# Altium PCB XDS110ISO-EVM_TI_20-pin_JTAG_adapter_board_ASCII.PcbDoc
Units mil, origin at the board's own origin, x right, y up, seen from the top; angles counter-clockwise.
Board outline 1100 x 500.17 mil, 2 copper layers (Top Signal, Bottom Signal), stack 58.8 mil thick; 2 components, 6 nets, 35 pads, 16 vias.
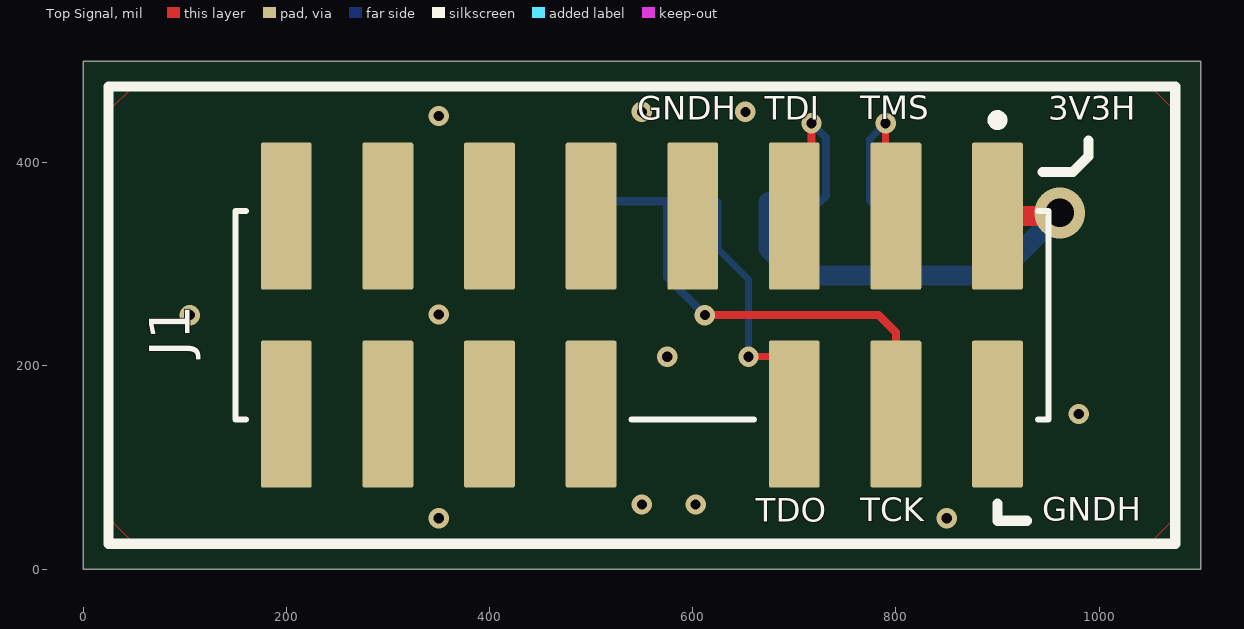
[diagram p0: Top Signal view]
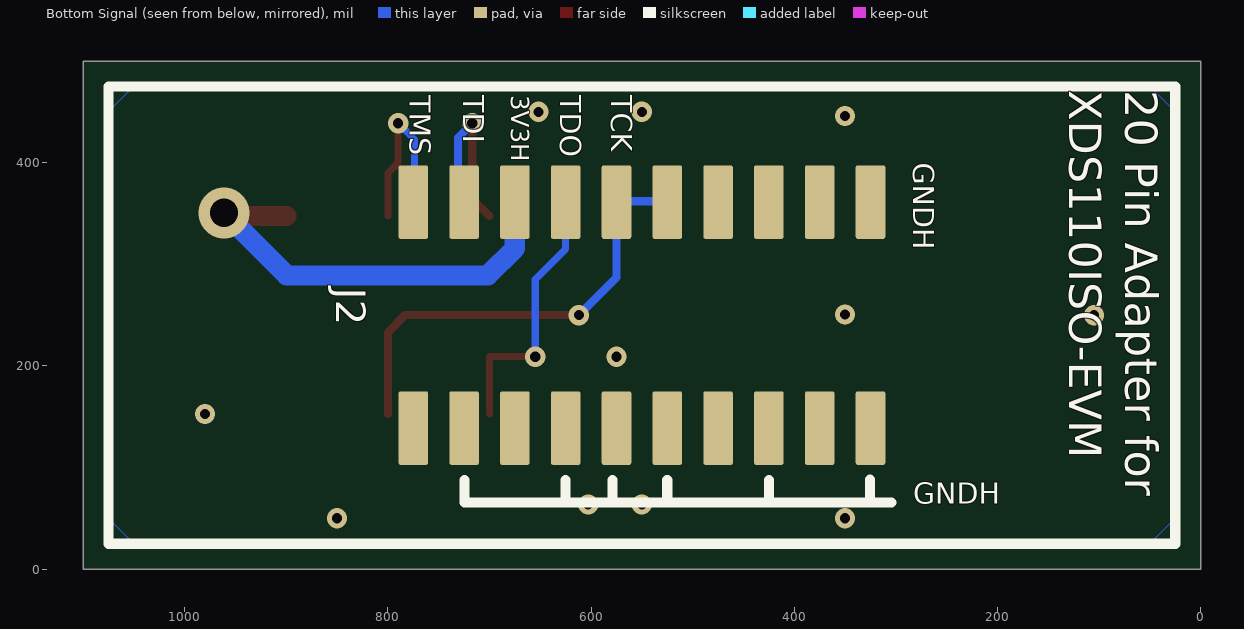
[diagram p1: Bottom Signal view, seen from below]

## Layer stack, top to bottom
Top Solder: solder mask 0.4, Solder Resist, Dk 3.5
Top Signal: signal copper 1.4
Dielectric 1: prepreg 8, FR-4, Dk 4.2
Dielectric 2: core 40, FR-4, Dk 4.2
Dielectric 3: prepreg 8, FR-4, Dk 4.2
Bottom Signal: signal copper 1.4
Bottom Solder: solder mask 0.4, Solder Resist, Dk 3.5

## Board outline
0,-0.17 0,500 1100,500 1100,-0.17

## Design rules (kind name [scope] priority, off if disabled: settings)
AcuteAngle [All] p0: scope1count=1 scope1_0_kind=Board scope1_0_value=Board scope2count=1 scope2_0_kind=Board scope2_0_value=Board commentlength=0 minimum=4.50000000000000E+0001
AcuteAngle [All] p1: minimum=4.50000000000000E+0001 checktracksonly=TRUE
AssemblyTestPointUsage [All] p0: scope1count=1 scope1_0_kind=Board scope1_0_value=Board scope2count=1 scope2_0_kind=Board scope2_0_value=Board commentlength=0
AssemblyTestPointUsage [All] p1: valid=2
AssemblyTestpoint [All] p0: scope1count=1 scope1_0_kind=Board scope1_0_value=Board scope2count=1 scope2_0_kind=Board scope2_0_value=Board commentlength=0
BoardOutlineClearance BoardOutlineClearance_USB101 [All] p0: scope1count=1 scope1_0_kind=Component scope1_0_value=USB101 scope2count=1 scope2_0_kind=Board scope2_0_value=Board commentlength=0 gap=0
BoardOutlineClearance [All] p0 off: scope1count=1 scope1_0_kind=Board scope1_0_value=Board scope2count=1 scope2_0_kind=Board scope2_0_value=Board commentlength=172 gap=10 // Protel DXP Scope 1 Expression Was: OnCopper and Not InComponentClass('Logo') and not InComponentClass('FiducialMark') and not InRegion(1000,500,4000,800) and not InPoly
BoardOutlineClearance BoardOutlineClearance_Poly [All] p0 off: scope1count=1 scope1_0_kind=Board scope1_0_value=Board scope2count=1 scope2_0_kind=Board scope2_0_value=Board commentlength=58 gap=25 // Protel DXP Scope 1 Expression Was: OnCopper and IsPoly
BoardOutlineClearance BoardOutlineClearance_MountingHoles [All] p0 off: scope1count=1 scope1_0_kind=Board scope1_0_value=Board scope2count=1 scope2_0_kind=Board scope2_0_value=Board commentlength=86 gap=40 // Protel DXP Scope 1 Expression Was: OnCopper and InComponentClass('Mounting Holes')
BoardOutlineClearance BoardOutlineClearance_MountingHoles [OnCopper and InComponentClass('Mounting Holes')] p1: gap=40 ignorepadtopadclearanceinfootprint=FALSE
BoardOutlineClearance BoardOutlineClearance_Poly [OnCopper and IsPoly] p2: gap=25 ignorepadtopadclearanceinfootprint=FALSE
BoardOutlineClearance BoardOutlineClearance_USB101 [InComponent('USB101')] p3: gap=0 ignorepadtopadclearanceinfootprint=FALSE
BoardOutlineClearance [OnCopper and Not InComponentClass('Logo') and not InComponentClass('FiducialMark') and not InRegion(1000,500,4000,800) and not InPoly] p4: gap=10 ignorepadtopadclearanceinfootprint=FALSE
Clearance Clearance_PTH [All] p0 off: scope1count=1 scope1_0_kind=Board scope1_0_value=Board scope2count=1 scope2_0_kind=Board scope2_0_value=Board commentlength=56 gap=7 // Protel DXP Scope 1 Expression Was: HoleDiameter > 10
Clearance Clearance_NPTH [All] p0 off: scope1count=1 scope1_0_kind=Board scope1_0_value=Board scope2count=1 scope2_0_kind=Board scope2_0_value=Board commentlength=56 gap=15 // Protel DXP Scope 1 Expression Was: HoleDiameter = 39
Clearance Clearance_FiducialMark [All] p0: scope1count=1 scope1_0_kind=ComponentClass scope1_0_value=FiducialMark scope2count=1 scope2_0_kind=ComponentClass scope2_0_value=FiducialMark commentlength=0 gap=0
Clearance Clearance_Boardedge [All] p0 off: scope1count=1 scope1_0_kind=Board scope1_0_value=Board scope2count=1 scope2_0_kind=Board scope2_0_value=Board commentlength=48 gap=11.8 // Protel DXP Scope 2 Expression Was: IsKeepOut
Clearance [All] p0: scope1count=1 scope1_0_kind=Board scope1_0_value=Board scope2count=1 scope2_0_kind=Board scope2_0_value=Board commentlength=0 gap=6
Clearance Clearance_NPTH [HoleDiameter = 39] p1: gap=15 ignorepadtopadclearanceinfootprint=FALSE
Clearance Clearance_PTH [HoleDiameter > 10] p2: gap=7 ignorepadtopadclearanceinfootprint=FALSE
Clearance Clearance_FiducialMark [InComponentClass('FiducialMark') vs InComponentClass('FiducialMark')] p3: gap=0 ignorepadtopadclearanceinfootprint=FALSE
Clearance Clearance_Boardedge [All vs IsKeepOut] p4: gap=11.8 ignorepadtopadclearanceinfootprint=FALSE
Clearance [All] p5: gap=6 ignorepadtopadclearanceinfootprint=FALSE
ComponentClearance ComponentClearance_THtoTH [All] p0 off: scope1count=1 scope1_0_kind=Board scope1_0_value=Board scope2count=1 scope2_0_kind=Board scope2_0_value=Board commentlength=54 gap=20 collisioncheckmode=3 // Protel DXP Scope 2 Expression Was: IsThruComponent
ComponentClearance ComponentClearance_THtoSMT [All] p0 off: scope1count=1 scope1_0_kind=Board scope1_0_value=Board scope2count=1 scope2_0_kind=Board scope2_0_value=Board commentlength=53 gap=10 collisioncheckmode=3 // Protel DXP Scope 2 Expression Was: IsSMTComponent
ComponentClearance ComponentClearance_SmallPassives [All] p0 off: scope1count=1 scope1_0_kind=Board scope1_0_value=Board scope2count=1 scope2_0_kind=Board scope2_0_value=Board commentlength=508 gap=10 collisioncheckmode=3 // Protel DXP Scope 2 Expression Was: HasFootprint('0201*') or HasFootprint('0402*') or HasFootprint('0508') or HasFootprint('0603*') or HasFootprint('0612') or HasFootprint('0805*') or HasFootprint('0815*') or HasFootprint('0830*') or HasFootprint('1206*') or HasFootprint('1210*') or HasFootprint('1808*') or HasFootprint('1812*') or HasFootprint('1825*') or HasFootprint('2010*') or HasFootprint('2220*') or HasFootprint('2225*') or HasFootprint('2512*') or HasFootprint('2728*') or HasFootprint('3518*')
ComponentClearance ComponentClearance_MountingHoles [All] p0 off: scope1count=1 scope1_0_kind=ComponentClass scope1_0_value="Mounting Holes" scope2count=1 scope2_0_kind=Board scope2_0_value=Board commentlength=0 gap=250 collisioncheckmode=3
ComponentClearance ComponentClearance_ScrewToNut [All] p0 off: scope1count=1 scope1_0_kind=Board scope1_0_value=Board scope2count=1 scope2_0_kind=Board scope2_0_value=Board commentlength=71 gap=3.94 collisioncheckmode=3 // Protel DXP Scope 2 Expression Was: (HasFootprint('Keystone_1902C'))
ComponentClearance ComponentClearance_Logo [All] p0: scope1count=1 scope1_0_kind=ComponentClass scope1_0_value=Logo scope2count=1 scope2_0_kind=Board scope2_0_value=Board commentlength=0 gap=0 collisioncheckmode=3
ComponentClearance ComponentClearance_Shunt [All] p0: scope1count=1 scope1_0_kind=ComponentClass scope1_0_value=Header scope2count=1 scope2_0_kind=ComponentClass scope2_0_value=Shunt commentlength=0 gap=0 collisioncheckmode=3
ComponentClearance ComponentClearance_MountingHoles_FiducialMarks [All] p0: scope1count=1 scope1_0_kind=ComponentClass scope1_0_value="Mounting Holes" scope2count=1 scope2_0_kind=ComponentClass scope2_0_value=FiducialMark commentlength=0 gap=50 collisioncheckmode=3
ComponentClearance ComponentClearance_Logo_1 [All] p0: scope1count=1 scope1_0_kind=ComponentClass scope1_0_value=Logo scope2count=1 scope2_0_kind=ComponentClass scope2_0_value=Logo commentlength=0 gap=0 collisioncheckmode=3
ComponentClearance "ComponentClearance_overlay to overlay" [All] p0 off: scope1count=1 scope1_0_kind=Board scope1_0_value=Board scope2count=1 scope2_0_kind=Board scope2_0_value=Board commentlength=54 gap=0 collisioncheckmode=3 // Protel DXP Scope 2 Expression Was: OnTopSilkscreen
ComponentClearance "ComponentClearance_overlay to overlay" [OnBottomSilkscreen vs OnTopSilkscreen] p1: gap=0 collisioncheckmode=3 verticalgap=0 showdistances=FALSE
ComponentClearance ComponentClearance_MountingHoles_FiducialMarks [InComponentClass('Mounting Holes') vs InComponentClass('FiducialMark')] p2: gap=50 collisioncheckmode=3 verticalgap=10 showdistances=FALSE
ComponentClearance ComponentClearance_Shunt [InComponentClass('Header') vs InComponentClass('Shunt')] p3: gap=0 collisioncheckmode=3 verticalgap=0 showdistances=FALSE
ComponentClearance ComponentClearance_Logo [InComponentClass('Logo')] p4: gap=0 collisioncheckmode=3 verticalgap=0 showdistances=FALSE
ComponentClearance ComponentClearance_Logo_1 [InComponentClass('Logo') vs InComponentClass('Logo')] p5: gap=0 collisioncheckmode=3 verticalgap=0 showdistances=FALSE
ComponentClearance ComponentClearance_ScrewToNut [(HasFootprint('NY PMS 440 0025 PH')) vs (HasFootprint('Keystone_1902C'))] p6: gap=3.94 collisioncheckmode=3 verticalgap=3.94 showdistances=FALSE
ComponentClearance ComponentClearance_MountingHoles [InComponentClass('Mounting Holes')] p7 off: gap=250 collisioncheckmode=3 verticalgap=100000 showdistances=FALSE
ComponentClearance ComponentClearance_SmallPassives [HasFootprint('0201*') or HasFootprint('0402*') or HasFootprint('0508') or HasFootprint('0603*') or HasFootprint('0612') or HasFootprint('0805*') or HasFootprint('0815*') or HasFootprint('0830*') or HasFootprint('1206*') or HasFootprint('1210*') or HasFootprint('1808*') or HasFootprint('1812*') or HasFootprint('1825*') or HasFootprint('2010*') or HasFootprint('2220*') or HasFootprint('2225*') or HasFootprint('2512*') or HasFootprint('2728*') or HasFootprint('3518*') vs HasFootprint('0201*') or HasFootprint('0402*') or HasFootprint('0508') or HasFootprint('0603*') or HasFootprint('0612') or HasFootprint('0805*') or HasFootprint('0815*') or HasFootprint('0830*') or HasFootprint('1206*') or HasFootprint('1210*') or HasFootprint('1808*') or HasFootprint('1812*') or HasFootprint('1825*') or HasFootprint('2010*') or HasFootprint('2220*') or HasFootprint('2225*') or HasFootprint('2512*') or HasFootprint('2728*') or HasFootprint('3518*')] p8 off: gap=10 collisioncheckmode=3 verticalgap=0 showdistances=FALSE
ComponentClearance ComponentClearance_THtoSMT [IsThruComponent vs IsSMTComponent] p9 off: gap=10 collisioncheckmode=3 verticalgap=10 showdistances=FALSE
ComponentClearance ComponentClearance_THtoTH [IsThruComponent vs IsThruComponent] p10 off: gap=20 collisioncheckmode=3 verticalgap=30 showdistances=FALSE
DiffPairsRouting [All] p0: scope1count=1 scope1_0_kind=Board scope1_0_value=Board scope2count=1 scope2_0_kind=Board scope2_0_value=Board commentlength=0
DiffPairsRouting [All] p1: maxlimit=100 minlimit=6 mostfreqgap=6 toplayer_minwidth=5.91 toplayer_maxwidth=15 toplayer_prefwidth=10.63 bottomlayer_minwidth=5.91 bottomlayer_maxwidth=15 bottomlayer_prefwidth=10.63 maxuncoupledlength=1000
FabricationTestPointUsage TestPointUsage [All] p0: scope1count=1 scope1_0_kind=Board scope1_0_value=Board scope2count=1 scope2_0_kind=Board scope2_0_value=Board commentlength=0 valid=2 allowmultiple=FALSE
FabricationTestPointUsage TestPointUsage [All] p1: valid=2 allowmultiple=FALSE
FabricationTestpoint Testpoint [All] p0: scope1count=1 scope1_0_kind=Board scope1_0_value=Board scope2count=1 scope2_0_kind=Board scope2_0_value=Board commentlength=0 side=3 testpointundercomponent=TRUE minsize=40 maxsize=100 preferedsize=60 minholesize=0 maxholesize=40 preferedholesize=32 testpointgrid=1
FabricationTestpoint Testpoint [All] p1: side=3 testpointundercomponent=TRUE minsize=40 maxsize=100 preferedsize=60 minholesize=0 maxholesize=40 preferedholesize=32 testpointgrid=1 allowsidetop=TRUE allowsidebottom=TRUE usegrid=TRUE gridtolerance=0.01
FanoutControl Fanout_Small [All] p0 off: scope1count=1 scope1_0_kind=Board scope1_0_value=Board scope2count=1 scope2_0_kind=Board scope2_0_value=Board commentlength=84 // Protel DXP Scope 1 Expression Was: (CompPinCount < 5)   Fanout_Small (Default Rule)
FanoutControl Fanout_Default [All] p0: scope1count=1 scope1_0_kind=Board scope1_0_value=Board scope2count=1 scope2_0_kind=Board scope2_0_value=Board commentlength=30 // Fanout_Default (Default Rule)
FanoutControl Fanout_SOIC [All] p0 off: scope1count=1 scope1_0_kind=Board scope1_0_value=Board scope2count=1 scope2_0_kind=Board scope2_0_value=Board commentlength=71 // Protel DXP Scope 1 Expression Was: IsSOIC   Fanout_SOIC (Default Rule)
FanoutControl Fanout_BGA [All] p0 off: scope1count=1 scope1_0_kind=Board scope1_0_value=Board scope2count=1 scope2_0_kind=Board scope2_0_value=Board commentlength=69 // Protel DXP Scope 1 Expression Was: IsBGA   Fanout_BGA (Default Rule)
FanoutControl Fanout_LCC [All] p0 off: scope1count=1 scope1_0_kind=Board scope1_0_value=Board scope2count=1 scope2_0_kind=Board scope2_0_value=Board commentlength=69 // Protel DXP Scope 1 Expression Was: IsLCC   Fanout_LCC (Default Rule)
FanoutControl Fanout_LCC [IsLCC] p1: bgadir=Out bgaviamode=Centered fanoutstyle=Auto fanoutdirection=Alternating viagrid=1 // Fanout_LCC (Default Rule)
FanoutControl Fanout_BGA [IsBGA] p2: bgadir=Out bgaviamode=Centered fanoutstyle=Auto fanoutdirection=Alternating viagrid=1 // Fanout_BGA (Default Rule)
FanoutControl Fanout_Default [All] p4: bgadir=Out bgaviamode=Centered fanoutstyle=Auto fanoutdirection=Alternating viagrid=1 // Fanout_Default (Default Rule)
FanoutControl Fanout_Small [(CompPinCount < 5)] p5: bgadir=Out bgaviamode=Centered fanoutstyle=Auto fanoutdirection=OutThenIn viagrid=1 // Fanout_Small (Default Rule)
Height [All] p0: scope1count=1 scope1_0_kind=Board scope1_0_value=Board scope2count=1 scope2_0_kind=Board scope2_0_value=Board commentlength=0
HoleSize [All] p0: scope1count=1 scope1_0_kind=Board scope1_0_value=Board scope2count=1 scope2_0_kind=Board scope2_0_value=Board commentlength=0 absolutevalues=TRUE maxlimit=251 minlimit=7.87 maxpercent=80.000 minpercent=20.000
HoleSize [All] p1: absolutevalues=TRUE maxlimit=251 minlimit=7.87 maxpercent=80.000 minpercent=20.000
HoleToHoleClearance HoleToHoleClearance_USB101 [All] p0: scope1count=1 scope1_0_kind=Component scope1_0_value=USB101 scope2count=1 scope2_0_kind=Component scope2_0_value=USB101 commentlength=0
HoleToHoleClearance [All] p0: scope1count=1 scope1_0_kind=Board scope1_0_value=Board scope2count=1 scope2_0_kind=Board scope2_0_value=Board commentlength=0
HoleToHoleClearance HoleToHoleClearance_USB101 [InComponent('USB101') vs InComponent('USB101')] p1: gap=0 allowstackedmicrovias=TRUE
HoleToHoleClearance [All] p2: gap=12 allowstackedmicrovias=TRUE
LayerPairs [All] p0: scope1count=1 scope1_0_kind=Board scope1_0_value=Board scope2count=1 scope2_0_kind=Board scope2_0_value=Board commentlength=0 enforce=TRUE
MatchedLengths FSIRX [All] p0: scope1count=1 scope1_0_kind=NetClass scope1_0_value=FSIRX scope2count=1 scope2_0_kind=Board scope2_0_value=Board commentlength=0 tolerance=25 amplitude=200 gap=20 style=90-Degree
MatchedLengths FSITX [All] p0: scope1count=1 scope1_0_kind=NetClass scope1_0_value=FSITX scope2count=1 scope2_0_kind=Board scope2_0_value=Board commentlength=0 tolerance=25 amplitude=200 gap=20 style=90-Degree
MatchedLengths FSIRX [InNetClass('FSIRX')] p1: tolerance=25 checknetsindiffpair=FALSE checkdiffpairvsdiffpair=TRUE checkxsignals=TRUE checkothers=TRUE
MatchedLengths FSITX [InNetClass('FSITX')] p2: tolerance=25 checknetsindiffpair=FALSE checkdiffpairvsdiffpair=TRUE checkxsignals=TRUE checkothers=TRUE
MinimumAnnularRing [All] p0: scope1count=1 scope1_0_kind=Board scope1_0_value=Board scope2count=1 scope2_0_kind=Board scope2_0_value=Board commentlength=0 minimumring=5
MinimumAnnularRing MinimumAnnularRing_ThermalPadVias [All] p0 off: scope1count=1 scope1_0_kind=Board scope1_0_value=Board scope2count=1 scope2_0_kind=Board scope2_0_value=Board commentlength=63 minimumring=5 // Protel DXP Scope 1 Expression Was: IsVia and InAnyComponent
MinimumAnnularRing MinimumAnnularRing_ThermalPadVias [IsVia and InAnyComponent] p1: minimumring=5
MinimumAnnularRing [All] p2: minimumring=5
MinimumSolderMaskSliver [All] p0: scope1count=1 scope1_0_kind=Board scope1_0_value=Board scope2count=1 scope2_0_kind=Board scope2_0_value=Board commentlength=0
MinimumSolderMaskSliver MinimumSolderMaskSliver_Logo [All] p0: scope1count=1 scope1_0_kind=ComponentClass scope1_0_value=Logo scope2count=1 scope2_0_kind=ComponentClass scope2_0_value=Logo commentlength=0
MinimumSolderMaskSliver MinimumSolderMaskSliver_Logo [InComponentClass('Logo') vs InComponentClass('Logo')] p1: minsoldermaskwidth=0.7
MinimumSolderMaskSliver [All] p2: minsoldermaskwidth=0
NetAntennae [All] p0: scope1count=1 scope1_0_kind=Board scope1_0_value=Board scope2count=1 scope2_0_kind=Board scope2_0_value=Board commentlength=0
PasteMaskExpansion [All] p0: scope1count=1 scope1_0_kind=Board scope1_0_value=Board scope2count=1 scope2_0_kind=Board scope2_0_value=Board commentlength=0 expansion=0
PlaneClearance [All] p0: scope1count=1 scope1_0_kind=Board scope1_0_value=Board scope2count=1 scope2_0_kind=Board scope2_0_value=Board commentlength=0 clearance=6
PlaneClearance [All] p1: clearance=6
PlaneConnect [All] p0: scope1count=1 scope1_0_kind=Board scope1_0_value=Board scope2count=1 scope2_0_kind=Board scope2_0_value=Board commentlength=0 planeconnectstyle=Relief reliefexpansion=7 reliefentries=4 reliefconductorwidth=8 reliefairgap=6
PlaneConnect [All] p1: planeconnectstyle=Relief reliefexpansion=7 reliefentries=4 reliefconductorwidth=8 reliefairgap=6
PolygonConnect PolygonConnect_GNDH [All] p0 off: scope1count=1 scope1_0_kind=Board scope1_0_value=Board scope2count=1 scope2_0_kind=Board scope2_0_value=Board commentlength=70 connectstyle=Relief reliefconductorwidth=30 reliefentries=4 polygonreliefangle="90 Angle" // Protel DXP Scope 1 Expression Was: InNet('GNDH') OR InNet('+3V3H')
PolygonConnect PolygonConnect_via [All] p0 off: scope1count=1 scope1_0_kind=Board scope1_0_value=Board scope2count=1 scope2_0_kind=Board scope2_0_value=Board commentlength=44 connectstyle=Relief reliefconductorwidth=8 reliefentries=4 polygonreliefangle="90 Angle" // Protel DXP Scope 1 Expression Was: isvia
PolygonConnect [All] p0: scope1count=1 scope1_0_kind=Board scope1_0_value=Board scope2count=1 scope2_0_kind=Board scope2_0_value=Board commentlength=0 connectstyle=Relief reliefconductorwidth=8 reliefentries=4 polygonreliefangle="90 Angle"
PolygonConnect PolygonConnect_via [isvia] p1: connectstyle=Relief reliefconductorwidth=8 reliefentries=4 polygonreliefangle="90 Angle" airgapwidth=6
PolygonConnect PolygonConnect_GNDH [InNet('GNDH') OR InNet('+3V3H')] p2: connectstyle=Relief reliefconductorwidth=30 reliefentries=4 polygonreliefangle="90 Angle" airgapwidth=6
PolygonConnect [All] p3: connectstyle=Relief reliefconductorwidth=8 reliefentries=4 polygonreliefangle="90 Angle" airgapwidth=6
RoutingCorners [All] p0: scope1count=1 scope1_0_kind=Board scope1_0_value=Board scope2count=1 scope2_0_kind=Board scope2_0_value=Board commentlength=0 cornerstyle=45-Degree minsetback=100 maxsetback=100
RoutingLayers [All] p0: scope1count=1 scope1_0_kind=Board scope1_0_value=Board scope2count=1 scope2_0_kind=Board scope2_0_value=Board commentlength=0 top layer=Automatic bottom layer=Automatic
RoutingPriority [All] p0: scope1count=1 scope1_0_kind=Board scope1_0_value=Board scope2count=1 scope2_0_kind=Board scope2_0_value=Board commentlength=0
RoutingTopology [All] p0: scope1count=1 scope1_0_kind=Board scope1_0_value=Board scope2count=1 scope2_0_kind=Board scope2_0_value=Board commentlength=0 topology=Shortest
RoutingVias RoutingVias_PWR [All] p0: scope1count=1 scope1_0_kind=Net scope1_0_value=+3V3H scope2count=1 scope2_0_kind=Board scope2_0_value=Board commentlength=0 holewidth=28 width=50 viastyle="Through Hole" minholewidth=28 minwidth=50 maxholewidth=28 maxwidth=50
RoutingVias [All] p0: scope1count=1 scope1_0_kind=Board scope1_0_value=Board scope2count=1 scope2_0_kind=Board scope2_0_value=Board commentlength=0 holewidth=10 width=20 viastyle="Through Hole" minholewidth=10 minwidth=20 maxholewidth=20 maxwidth=40
RoutingVias ThermalPadVias [All] p0: scope1count=1 scope1_0_kind=Board scope1_0_value=Board scope2count=1 scope2_0_kind=Board scope2_0_value=Board commentlength=0 holewidth=10 width=20 viastyle="Through Hole" minholewidth=10 minwidth=20 maxholewidth=20 maxwidth=40
RoutingVias RoutingVias_PWR [InNet('+3V3H')] p1: holewidth=28 width=50 viastyle="Through Hole" minholewidth=28 minwidth=50 maxholewidth=28 maxwidth=50
RoutingVias ThermalPadVias [All] p2: holewidth=10 width=20 viastyle="Through Hole" minholewidth=10 minwidth=20 maxholewidth=20 maxwidth=40
RoutingVias [All] p3: holewidth=10 width=20 viastyle="Through Hole" minholewidth=10 minwidth=20 maxholewidth=20 maxwidth=40
ShortCircuit [All] p0: scope1count=1 scope1_0_kind=Board scope1_0_value=Board scope2count=1 scope2_0_kind=Board scope2_0_value=Board commentlength=0 allowed=FALSE
SilkToBoardRegionClearance [All] p0 off: scope1count=1 scope1_0_kind=Board scope1_0_value=Board scope2count=1 scope2_0_kind=Board scope2_0_value=Board commentlength=130 // Protel DXP Scope 1 Expression Was: Not ((IsComment or IsDesignator) And (Hide <> 'False')) and not InRegion(1000,500,4000,800)
SilkToBoardRegionClearance [Not ((IsComment or IsDesignator) And (Hide <> 'False')) and not InRegion(1000,500,4000,800)] p1:
SilkToSilkClearance [All] p0: scope1count=1 scope1_0_kind=Board scope1_0_value=Board scope2count=1 scope2_0_kind=Board scope2_0_value=Board commentlength=0
SilkToSilkClearance SilkToSilkClearance_Pb-FreeLogo [All] p0 off: scope1count=1 scope1_0_kind=Board scope1_0_value=Board scope2count=1 scope2_0_kind=Board scope2_0_value=Board commentlength=120 // Protel DXP Scope 2 Expression Was: (HasFootprint('Pb-Free_Overlay_Medium') OR HasFootprint('Pb-Free_Overlay_Small'))
SilkToSilkClearance SilkToSilkClearance_Pb-FreeLogo [(HasFootprint('Pb-Free_Overlay_Medium') OR HasFootprint('Pb-Free_Overlay_Small')) vs (HasFootprint('Pb-Free_Overlay_Medium') OR HasFootprint('Pb-Free_Overlay_Small'))] p1: silktosilkclearance=0
SilkToSilkClearance [All] p2: silktosilkclearance=3
SilkToSolderMaskClearance "Silk to Solder Mask Opening" [All] p0: scope1count=1 scope1_0_kind=Board scope1_0_value=Board scope2count=1 scope2_0_kind=Board scope2_0_value=Board commentlength=0
SilkToSolderMaskClearance SilkToComponentPadClearance [All] p0 off: scope1count=1 scope1_0_kind=Board scope1_0_value=Board scope2count=1 scope2_0_kind=Board scope2_0_value=Board commentlength=87 // Protel DXP Scope 1 Expression Was: (IsPad or IsFill or IsRegion) and InAnycomponent
SilkToSolderMaskClearance SilkToComponentPadClearance [(IsPad or IsFill or IsRegion) and InAnycomponent] p1: minsilkscreentomaskgap=2.5 clearancetoexposedcopper=TRUE
SilkToSolderMaskClearance "Silk to Solder Mask Opening" [All] p2: minsilkscreentomaskgap=2.5 clearancetoexposedcopper=TRUE
SolderMaskExpansion [All] p0: scope1count=1 scope1_0_kind=Board scope1_0_value=Board scope2count=1 scope2_0_kind=Board scope2_0_value=Board commentlength=0 expansion=2
SolderMaskExpansion [All] p1: expansion=2 istentingtop=FALSE
UnRoutedNet [All] p0: scope1count=1 scope1_0_kind=Board scope1_0_value=Board scope2count=1 scope2_0_kind=Board scope2_0_value=Board commentlength=0
UnRoutedNet [All] p1: checkbadconnections=TRUE
UnpouredPolygon [All] p0: scope1count=1 scope1_0_kind=Board scope1_0_value=Board scope2count=1 scope2_0_kind=Board scope2_0_value=Board commentlength=0
Width [All] p0: scope1count=1 scope1_0_kind=Board scope1_0_value=Board scope2count=1 scope2_0_kind=Board scope2_0_value=Board commentlength=0 maxlimit=100 minlimit=7 preferedwidth=8
Width Analog [All] p0: scope1count=1 scope1_0_kind=NetClass scope1_0_value=Analog scope2count=1 scope2_0_kind=Board scope2_0_value=Board commentlength=0 maxlimit=25 minlimit=8 preferedwidth=8
Width Analog [InNetClass('Analog')] p1: maxlimit=25 minlimit=8 preferedwidth=8
Width [All] p2: maxlimit=100 minlimit=7 preferedwidth=8 minimp=50.000000 maximp=50.000000 favimp=50.000000 checkconnectedcopper=TRUE
12 further rules are at their usual default settings.

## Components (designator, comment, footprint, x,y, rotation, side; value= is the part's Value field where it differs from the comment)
J1 "TSM-108-01-L-DV-008-P-TR" FP-TSM-108-01-L-DV-008-P-TR_HDR15-MFG 550,250 r180 top
J2 "RSM-110-02-L-D" Samtec_RSM-110-02-x-D 550,250 r180 bottom

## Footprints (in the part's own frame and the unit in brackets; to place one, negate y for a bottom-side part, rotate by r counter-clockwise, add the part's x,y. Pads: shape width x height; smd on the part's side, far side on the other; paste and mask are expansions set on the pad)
FP-TSM-108-01-L-DV-008-P-TR_HDR15-MFG [mm]
  rrect8% 1.27x3.68 smd paste+0 mask+0: 1(-8.89,-2.475) 2(-8.89,2.475) 3(-6.35,-2.475) 4(-6.35,2.475) 5(-3.81,-2.475) 6(-3.81,2.475) 7(-1.27,-2.475) 9(1.27,-2.475) 10(1.27,2.475) 11(3.81,-2.475) 12(3.81,2.475) 13(6.35,-2.475) 14(6.35,2.475) 15(8.89,-2.475) 16(8.89,2.475)
  silkscreen extent -10.16,-5 10.16,2.6
Samtec_RSM-110-02-x-D [mm] "Receptacle, 1.27mm, 10x2, SMT"
  rrect14% 0.74x1.84 smd: 1(-5.715,2.825) 2(-5.715,-2.825) 3(-4.445,2.825) 4(-4.445,-2.825) 5(-3.175,2.825) 6(-3.175,-2.825) 7(-1.905,2.825) 8(-1.905,-2.825) 9(-0.635,2.825) 10(-0.635,-2.825) 11(0.635,2.825) 12(0.635,-2.825) 13(1.905,2.825) 14(1.905,-2.825) 15(3.175,2.825) 16(3.175,-2.825) 17(4.445,2.825) 18(4.445,-2.825) 19(5.715,2.825) 20(5.715,-2.825)

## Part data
J1: library part CMP-0121706-1, "Conn Unshrouded HDR 16 POS 2.54mm Solder ST SMT"
J2: library part CMP-0081743-1, "Receptacle, 1.27mm, 10x2, Gold with Tin tail, SMT"

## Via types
v1: diameter 20, hole 10, Top Signal to Bottom Signal, tented both sides, 15 vias
v2: diameter 50, hole 28, Top Signal to Bottom Signal, tented both sides, 1 vias

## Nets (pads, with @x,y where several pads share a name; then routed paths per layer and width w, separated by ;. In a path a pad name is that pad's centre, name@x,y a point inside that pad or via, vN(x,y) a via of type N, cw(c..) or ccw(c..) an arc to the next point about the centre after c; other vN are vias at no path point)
+3V3H: J1.1 J2.5 | length 431.1
  Top Signal w20: J1.1 958.17,347.44 v2(961.29,350.55)
  Bottom Signal w20: J2.5 675,315.49 701.49,289 775,289 899.73,289 v2(961.29,350.55)
GNDH: J1.2 J1.7 J2.4 J2.8 J2.10 J2.12 J2.16 J2.19 J2.20
  other v1: 350,50 850,50 550,63.56 602.94,63.56 980,152.56 575,209.06 105,249.99 350,250.65 350,446 550,450 651.82,450
MCU_TCK: J1.4 J2.9 J2.11 | length 453.6
  Top Signal w8: v1(612,249.99) 783,249.99 800,232.99 J1.4
  Bottom Signal w8: J2.11 525,361.99 575,361.99 J2.9 575,286.99 v1(612,249.99)
MCU_TDI: J1.5 J2.3 | length 184.3
  Top Signal w8: J1.5 717,364.44 v1(717,438.75)
  Bottom Signal w8: v1(717,438.75) 731.16,424.59 731.16,367.38 J2.3
MCU_TDO: J1.6 J2.7 | length 266.1
  Top Signal w7: v1(655,209.06) 700,209.06 J1.6
  Bottom Signal w7: J2.7 625,315 655,285 v1(655,209.06)
MCU_TMS: J1.3 J2.1 | length 180.1
  Top Signal w7: v1(789.88,438.75) 789.88,400 800,389.88 J1.3
  Bottom Signal w7: J2.1 773.88,362.34 773.88,422.75 v1(789.88,438.75)
pads on no net: J1.9 J1.10 J1.11 J1.12 J1.13 J1.14 J1.15 J1.16 J2.2 J2.6 J2.13 J2.14 J2.15 J2.17 J2.18

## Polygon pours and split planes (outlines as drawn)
GNDH on Bottom Signal "NONET_L-01_P-001" (solid, remove dead copper, pour order 22): 1050,475 50,475 25,450 25,50 50,25 1050,25 1075,50 1075,450
GNDH on Top Signal "NONET_L-01_P-001" (solid, remove dead copper, pour order 15): 50,475 25,450.81 25,50.49 50,25.49 1050,25.49 1075,50.49 1075.22,450.81 1050,475

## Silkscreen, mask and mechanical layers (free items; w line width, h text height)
Top Overlay:
  lines w10: 900,64.38 900,47.63 928.89,47.63 ; 944.39,390.81 974.21,390.81 989.65,406.25 989.65,421.82 ; 25,25 1075,25 1075,475 25,475 25,25
  text "TMS" at 765,434.8 h40
  text "GNDH" at 545.56,434.3 h40
  text "TDI" at 670.72,434.3 h40
  text "3V3H" at 950,434.3 h40
  text "GNDH" at 943.94,39.64 h40
  text "TDO" at 662.24,38.73 h40
  text "TCK" at 765,39.22 h40
Bottom Overlay:
  lines w10: 25,474.51 25,25 1075,25 1075,474.51 ; 25,475 1075,475 ; 304.28,65.53 724.44,65.53 724.44,87.4 ; 325.51,65.53 325.51,87.91 ; 425,65.53 425,87.4 ; 525,65.53 525,87.4 ; 579,65.53 579,87.4 ; 625.01,65.53 625.01,87.4
  text "20 Pin Adapter for / XDS110ISO-EVM" at 140,471.48 h55 r90
  text "TCK" at 587,466.57 h35 r90
  text "TDO" at 637.16,466.57 h35 r90
  text "3V3H" at 684.51,466.57 h30 r90
  text "TDI" at 732.87,466.57 h35 r90
  text "TMS" at 785.57,466.57 h35 r90
  text "GNDH" at 289.63,400 h35 r90
  text "GNDH" at 283,57.37 h35
M1 Board Outline:
  the board outline again, w10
